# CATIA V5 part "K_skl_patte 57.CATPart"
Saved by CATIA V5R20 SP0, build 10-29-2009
Part number: skl_patte 57
Publications: "longueur axe pivot", "liaison 57/23", "liaison 57/50", "Plan.-30", "Droite.1", "Droite.2", "Droite.3"
Bounding box of the stored display mesh (mm): x -180 to -30, y -720 to -660, z 725 to 795
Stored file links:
  G:\Khaled_CFAO_2011\SIL\SIL_GR2\mdardier\Khaled\CAD_ThinkMOTION\K_skl_patte 57.CATPart
  G:\Khaled_CFAO_2011\SIL\SIL_GR2\mdardier\Khaled\CAD_ThinkMOTION\K_skl_ass_tandem.CATProduct
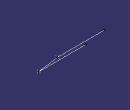
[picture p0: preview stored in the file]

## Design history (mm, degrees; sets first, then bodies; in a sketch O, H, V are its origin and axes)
External parameters (linked from other documents)
  `External.longueur axe pivot` = 150 mm
Set1
  Point1 "liaison 57/23": linked copy from another document
  Point2 "liaison 57/50": linked copy from another document
  Plane1 "Plan.-30": linked copy from another document
Set2
  Line1: type PtPt, FirstPoint Point1, SecondPoint Point2
  Line2: type Normal, RefPoint Point1, RefSkin Plane1, Start 0, End 150 {= `External.longueur axe pivot`}
  Line3: type Normal, RefPoint Point2, RefSkin Plane1, Start 0, End 150 {= `External.longueur axe pivot`}
Body1 (main body)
